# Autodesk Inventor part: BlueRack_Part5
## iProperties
Shininess: 64.0
Length Units: 11272
Angle Units: 11279
Time Units: 11290
Mass Units: 11286
Length Display Precision: 3
Angle Display Precision: 2
Compacted: True
Part Number: BlueRack_Part5
Document SubType Name: Modeling
Created: 2004-12
Designer: John Blackburn
Manufacturer: Standard
Standards Organization: Custom
Material: Steel, Mild
Density: 0.0
Volumn: 0.0
Area: 0.0
PropertySet Name: Model Information
Control State: 0
Master: False
Checked Out: False
Author: John Blackburn
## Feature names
1. Extrusion1
